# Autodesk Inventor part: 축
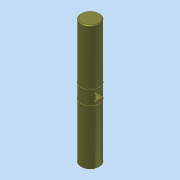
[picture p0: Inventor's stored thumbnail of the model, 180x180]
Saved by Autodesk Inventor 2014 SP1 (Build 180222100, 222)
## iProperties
Company: 한국ATC센터
Created: 2015-04
Part Number: 축
Document SubType Name: Modeling
Designer: KYOUNG IL JANG
Density: 7.85 g/cm^3
Material: 강
Appearance: 티타늄
Author: KYOUNG IL JANG
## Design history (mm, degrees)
sketch "스케치1"
  geometry: C1 r 11 at (0, 0); 1 further point
  constraints: 1 centre point, 1 coincident
  dimensions: "d0" = 22 diameter of C1
extrude "돌출1" new body sketch "스케치1" stored distance "d1" = 150; taper "d2" = 0 deg
sketch "스케치2"
  geometry: L1 (-10.247, -4)-(10.247, -4); L2 (-10.247, 4)-(10.247, 4); A1 r 11 centre (0, 0) between (-10.247, -4) and (10.247, -4) reference; 1 further point
  constraints: 4 end point, 4 point on circle, 2 parallel, 1 horizontal
  dimensions: "d3" = 8 distance between parallel lines of L2 L1
extrude "돌출2" cut sketch "스케치2" stored distance "d4" = 8; taper "d5" = 0 deg
sketch "스케치3"
  geometry: 5 further points
hole "구멍1" sketch "스케치3" at (-4, 4), (4, 4), (4, -4), (-4, -4) diameter "d6" = 2; stored, may be unused: countersink angle "d10" = 90 deg, drill point angle "d12" = 118 deg; dims "d7" = 6, "d8" = 4, "d9" = 2, "d11" = 8
chamfer "모따기1" distance "d13" = 1; stored, may be unused: second distance "d14" = 2, angle "d15" = 45 deg
sketch "스케치4"
  geometry: L1 (-10, 9)-(-11, 9); L2 (-11, 9)-(-11, 7.8); L3 (-11, 7.8)-(-10, 7.8); L4 (-10, 7.8)-(-10, 9); L5 (-10, 75)-(10, 75) reference; L6 (0, -10)-(0, 60) reference; 1 further point
  constraints: 8 end point, 2 parallel, 1 horizontal, 1 perpendicular
  dimensions: "d16" = 7.8 distance from line of L3 point (0, 0); "d17" = 67.2 distance between parallel lines of L3 L5 (derived); "d18" = 11 distance from line of point (0, 0) L2; "d19" = 1 distance of L2.end L3.end; "d20" = 1.2 distance of L1.end L2.end
revolve "회전1" sketch "스케치4" stored, may be unused: angle "d21" = 90 deg
node "솔리드1"
mirror "대칭1"
mirror "대칭2"
